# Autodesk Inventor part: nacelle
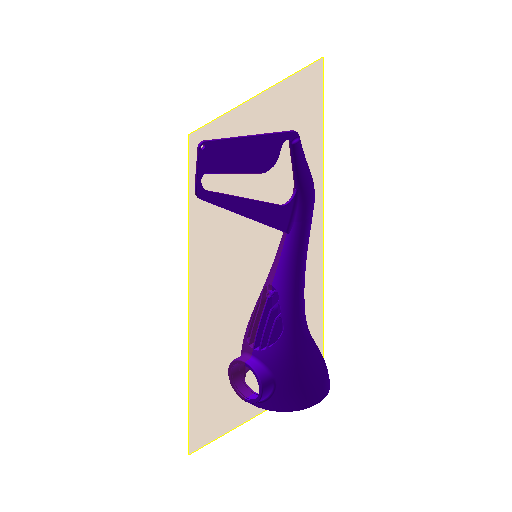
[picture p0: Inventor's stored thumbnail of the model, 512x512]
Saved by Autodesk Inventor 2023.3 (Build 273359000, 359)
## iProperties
Created: 2014-09
Part Number: nacelle
Material: Aluminium 6061
Document SubType Name: Modeling
Designer: papa
Density: 2.7 g/cm^3
Appearance: Aluminium - Plat
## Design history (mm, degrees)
node "nacelle1"
sketch "Esquisse1"
  geometry: A1 r 1.75 centre (0, 65.493) between (-0.9, 66.994) and (0.9, 66.994) reference; 2 further points
  dimensions: "d7" = 0 distance of A1.centre point (0, 65.493); "d8" = 0 distance of A1.centre point (0, 65.493)
hole "Perçage1" sketch "Esquisse1" at (0, 65.493) diameter "d0" = 4.134; stored, may be unused: countersink angle "d4" = 90 deg, drill point angle "d6" = 118 deg; dims "d1" = 10, "d2" = 4, "d3" = 2, "d5" = 14.2
pattern_circular "Réseau circulaire1" dims angle "d10" = 360 deg
sketch "Esquisse2"
  geometry: C1 r 2 at (-37, 17) reference; 2 further points
  dimensions: "d19" = 0 distance of point (-37, 17) C1.centre; "d20" = 0 distance of point (-37, 17) C1.centre
hole "Perçage2" sketch "Esquisse2" at (-37, 17) diameter "d12" = 4.134; stored, may be unused: countersink angle "d16" = 90 deg, drill point angle "d18" = 118 deg; dims "d13" = 10, "d14" = 4, "d15" = 2, "d17" = 14.2
pattern_linear "Réseau rectangulaire1" dims "d23" = 74
node "nacelle"
node "Base1"
